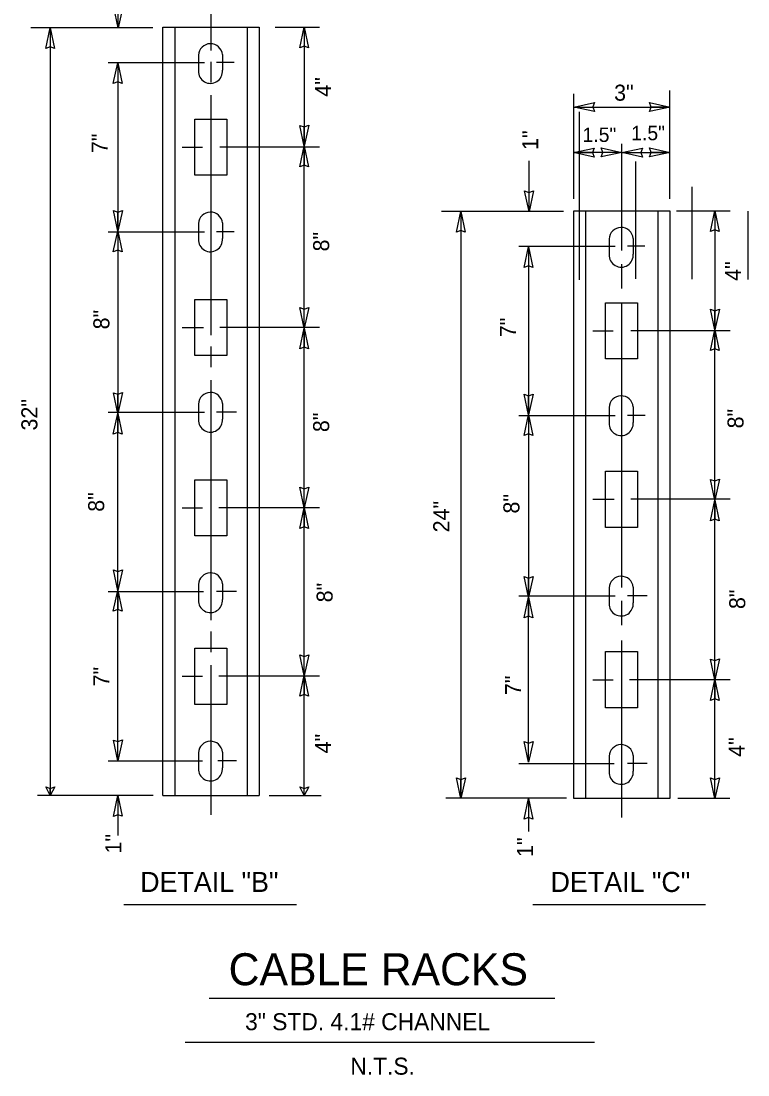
# Model space of a CAD drawing. Extents: x 19188 to 19495, y 20866 to 21061.
# Drawn here: x 19209.5 to 19245.3, y 20881.1 to 20932.9 of the extents above; entities that cross this region are included whole.
import ezdxf

# ---------------------------------------------------------------- set-up
doc = ezdxf.new("R2010")
doc.units = 0
doc.layers.add('G-ANNO-NOTE', color=7, linetype='Continuous')

msp = doc.modelspace()

# ---------------------------------------------------------------- linework, layer by layer
at = {"layer": 'G-ANNO-NOTE'}
for p, q in [((19214.31, 20932.566), (19214.31, 20935.058)), ((19214.31, 20932.566), (19214.31, 20933.502)), ((19216.005, 20932.566), (19210.015, 20932.566)), ((19210.966, 20932.566), (19210.966, 20894.812)), ((19210.966, 20932.566), (19210.966, 20931.63)), ((19216.507, 20932.592), (19221.237, 20932.592)), ((19216.507, 20894.812), (19216.507, 20932.592)), ((19217.098, 20894.812), (19217.098, 20932.592)), ((19220.645, 20932.592), (19220.645, 20894.812)), ((19221.237, 20932.592), (19221.237, 20894.812)), ((19222.022, 20932.598), (19224.196, 20932.598)), ((19223.449, 20932.598), (19223.449, 20926.749)), ((19223.449, 20932.598), (19223.449, 20931.662)), ((19218.247, 20931.206), (19218.247, 20930.417)), ((19219.429, 20931.242), (19219.429, 20930.473)), ((19213.809, 20930.857), (19218.55, 20930.857)), ((19214.289, 20930.832), (19214.29, 20922.564)), ((19214.289, 20930.832), (19214.289, 20929.896)), ((19220.011, 20930.857), (19219.145, 20930.857)), ((19236.689, 20924.149), (19236.689, 20929.309)), ((19241.419, 20924.149), (19241.419, 20929.486)), ((19236.689, 20928.666), (19241.437, 20928.666)), ((19236.689, 20928.666), (19237.625, 20928.666)), ((19241.437, 20928.666), (19240.5, 20928.666)), ((19218.069, 20928.073), (19219.646, 20928.073)), ((19218.069, 20925.314), (19218.069, 20928.073)), ((19219.646, 20928.073), (19219.646, 20925.314)), ((19236.964, 20928.421), (19236.964, 20920.177)), ((19236.964, 20928.421), (19236.964, 20920.177)), ((19223.449, 20926.749), (19223.449, 20927.685)), ((19217.454, 20926.694), (19218.441, 20926.694)), ((19224.196, 20926.694), (19219.308, 20926.694)), ((19223.449, 20917.789), (19223.449, 20926.749)), ((19223.449, 20926.749), (19223.449, 20925.812)), ((19234.493, 20923.531), (19234.493, 20926.023)), ((19239.054, 20926.432), (19236.683, 20926.432)), ((19236.683, 20926.432), (19237.619, 20926.432)), ((19239.054, 20926.432), (19238.118, 20926.432)), ((19239.054, 20926.432), (19241.437, 20926.432)), ((19239.054, 20926.432), (19239.991, 20926.432)), ((19239.73, 20925.981), (19239.73, 20920.224)), ((19239.73, 20925.981), (19239.73, 20920.224)), ((19241.437, 20926.432), (19240.5, 20926.432)), ((19219.646, 20925.314), (19218.069, 20925.314)), ((19234.493, 20923.531), (19234.493, 20924.467)), ((19242.495, 20924.743), (19242.495, 20920.206)), ((19242.495, 20924.743), (19242.495, 20920.206)), ((19214.29, 20922.564), (19214.29, 20923.501)), ((19236.187, 20923.531), (19230.198, 20923.531)), ((19231.149, 20923.531), (19231.149, 20894.67)), ((19231.149, 20923.531), (19231.149, 20922.595)), ((19236.689, 20923.558), (19241.419, 20923.558)), ((19236.689, 20894.67), (19236.689, 20923.558)), ((19237.28, 20894.67), (19237.28, 20923.558)), ((19240.828, 20923.558), (19240.828, 20894.67)), ((19241.419, 20923.558), (19241.419, 20894.67)), ((19241.746, 20923.564), (19244.378, 20923.564)), ((19243.631, 20923.564), (19243.631, 20917.714)), ((19243.631, 20923.564), (19243.631, 20922.627)), ((19245.25, 20923.548), (19245.25, 20920.191)), ((19245.25, 20923.548), (19245.25, 20920.191)), ((19218.247, 20922.928), (19218.247, 20922.14)), ((19219.429, 20922.964), (19219.429, 20922.195)), ((19213.81, 20922.533), (19218.55, 20922.534)), ((19214.29, 20922.564), (19214.291, 20913.605)), ((19214.29, 20922.564), (19214.29, 20921.628)), ((19220.011, 20922.534), (19219.145, 20922.534)), ((19233.992, 20921.822), (19238.732, 20921.822)), ((19238.429, 20922.171), (19238.429, 20921.382)), ((19240.193, 20921.822), (19239.328, 20921.822)), ((19239.612, 20922.207), (19239.612, 20921.438)), ((19234.471, 20921.798), (19234.472, 20913.53)), ((19234.471, 20921.798), (19234.471, 20920.862)), ((19218.069, 20919.205), (19219.646, 20919.205)), ((19218.069, 20916.445), (19218.069, 20919.205)), ((19219.646, 20919.205), (19219.646, 20916.445)), ((19223.449, 20917.789), (19223.449, 20918.725)), ((19238.251, 20919.039), (19239.828, 20919.039)), ((19238.251, 20916.28), (19238.251, 20919.039)), ((19239.828, 20919.039), (19239.828, 20916.28)), ((19243.631, 20917.714), (19243.631, 20918.65)), ((19217.455, 20917.825), (19218.495, 20917.825)), ((19224.196, 20917.825), (19219.308, 20917.825)), ((19223.449, 20908.956), (19223.449, 20917.789)), ((19223.449, 20917.789), (19223.449, 20916.853)), ((19243.631, 20909.346), (19243.631, 20917.714)), ((19243.631, 20917.714), (19243.631, 20916.778)), ((19237.637, 20917.659), (19238.624, 20917.659)), ((19244.378, 20917.659), (19239.49, 20917.659)), ((19219.646, 20916.445), (19218.069, 20916.445)), ((19239.828, 20916.28), (19238.251, 20916.28)), ((19214.291, 20913.605), (19214.29, 20914.541)), ((19218.247, 20914.059), (19218.247, 20913.271)), ((19219.429, 20914.095), (19219.429, 20913.326)), ((19234.472, 20913.53), (19234.472, 20914.466)), ((19213.81, 20913.665), (19218.55, 20913.665)), ((19214.291, 20904.899), (19214.291, 20913.605)), ((19214.291, 20913.605), (19214.291, 20912.668)), ((19220.118, 20913.665), (19219.145, 20913.665)), ((19234.472, 20913.53), (19234.473, 20904.57)), ((19234.472, 20913.53), (19234.472, 20912.594)), ((19238.429, 20913.893), (19238.429, 20913.105)), ((19239.612, 20913.929), (19239.612, 20913.16)), ((19233.992, 20913.499), (19238.732, 20913.499)), ((19240.194, 20913.499), (19239.328, 20913.499)), ((19238.251, 20910.761), (19239.828, 20910.761)), ((19238.251, 20908.002), (19238.251, 20910.761)), ((19239.828, 20910.761), (19239.828, 20908.002)), ((19218.069, 20910.336), (19219.646, 20910.336)), ((19218.069, 20907.577), (19218.069, 20910.336)), ((19219.646, 20910.336), (19219.646, 20907.577)), ((19243.631, 20909.346), (19243.631, 20910.282)), ((19223.449, 20908.956), (19223.449, 20909.892)), ((19237.637, 20909.381), (19238.678, 20909.381)), ((19244.378, 20909.382), (19239.49, 20909.381)), ((19217.455, 20908.956), (19218.441, 20908.956)), ((19224.196, 20908.956), (19219.254, 20908.956)), ((19223.449, 20900.715), (19223.449, 20908.956)), ((19223.449, 20908.956), (19223.449, 20908.02)), ((19243.631, 20900.513), (19243.631, 20909.346)), ((19243.631, 20909.346), (19243.631, 20908.409)), ((19239.828, 20908.002), (19238.251, 20908.002)), ((19219.646, 20907.577), (19218.069, 20907.577)), ((19214.291, 20904.899), (19214.291, 20905.835)), ((19234.473, 20904.57), (19234.472, 20905.506)), ((19213.811, 20904.842), (19218.495, 20904.842)), ((19214.291, 20896.53), (19214.291, 20904.899)), ((19214.291, 20904.899), (19214.291, 20903.962)), ((19218.247, 20905.19), (19218.247, 20904.402)), ((19220.118, 20904.842), (19219.145, 20904.842)), ((19219.429, 20905.226), (19219.429, 20904.458)), ((19238.429, 20905.025), (19238.429, 20904.236)), ((19239.612, 20905.061), (19239.612, 20904.292)), ((19233.992, 20904.63), (19238.732, 20904.631)), ((19234.473, 20896.455), (19234.473, 20904.57)), ((19234.473, 20904.57), (19234.473, 20903.634)), ((19240.3, 20904.631), (19239.328, 20904.631)), ((19218.069, 20902.058), (19219.646, 20902.058)), ((19218.069, 20899.299), (19218.069, 20902.058)), ((19219.646, 20902.058), (19219.646, 20899.299)), ((19223.449, 20900.715), (19223.449, 20901.651)), ((19238.251, 20901.892), (19239.828, 20901.892)), ((19238.251, 20899.133), (19238.251, 20901.892)), ((19239.828, 20901.892), (19239.828, 20899.133)), ((19243.631, 20900.513), (19243.631, 20901.449)), ((19217.455, 20900.679), (19218.441, 20900.679)), ((19224.196, 20900.679), (19219.254, 20900.679)), ((19223.449, 20900.715), (19223.449, 20899.778)), ((19223.449, 20894.812), (19223.449, 20900.715)), ((19237.637, 20900.513), (19238.624, 20900.513)), ((19244.378, 20900.513), (19239.436, 20900.513)), ((19243.631, 20900.513), (19243.631, 20899.577)), ((19243.631, 20894.67), (19243.631, 20900.513)), ((19219.646, 20899.299), (19218.069, 20899.299)), ((19239.828, 20899.133), (19238.251, 20899.133)), ((19214.291, 20896.53), (19214.291, 20897.467)), ((19219.429, 20896.949), (19219.429, 20896.18)), ((19234.473, 20896.455), (19234.473, 20897.391)), ((19213.812, 20896.518), (19218.441, 20896.519)), ((19218.247, 20896.913), (19218.247, 20896.125)), ((19220.119, 20896.519), (19219.2, 20896.519)), ((19238.429, 20896.747), (19238.429, 20895.959)), ((19239.612, 20896.783), (19239.612, 20896.014)), ((19233.993, 20896.398), (19238.678, 20896.398)), ((19240.301, 20896.399), (19239.328, 20896.398)), ((19231.149, 20894.67), (19231.149, 20895.606)), ((19243.631, 20894.67), (19243.631, 20895.606)), ((19210.966, 20894.812), (19210.966, 20895.158)), ((19223.449, 20894.812), (19223.449, 20895.158)), ((19216.032, 20894.812), (19210.335, 20894.812)), ((19214.292, 20894.812), (19214.292, 20892.854)), ((19214.292, 20894.812), (19214.292, 20893.876)), ((19216.507, 20894.812), (19221.237, 20894.812)), ((19221.728, 20894.812), (19224.286, 20894.812)), ((19236.334, 20894.687), (19230.41, 20894.687)), ((19234.473, 20894.67), (19234.474, 20893.048)), ((19234.473, 20894.67), (19234.474, 20893.734)), ((19241.419, 20894.67), (19236.689, 20894.67)), ((19241.803, 20894.687), (19244.367, 20894.687)), ((19214.581, 20889.468), (19223.071, 20889.468)), ((19234.684, 20889.468), (19243.174, 20889.468)), ((19218.77, 20884.853), (19235.767, 20884.853)), ((19217.592, 20882.698), (19237.705, 20882.698))]:
    msp.add_line(p, q, dxfattribs=at)
for points in [[(19218.872, 20931.451), (19218.872, 20935.886)], [(19214.31, 20933.503), (19214.534, 20933.584), (19214.31, 20932.566), (19214.097, 20933.582), (19214.31, 20933.503)], [(19210.966, 20931.63), (19210.743, 20931.548), (19210.966, 20932.566), (19211.18, 20931.55), (19210.966, 20931.63)], [(19223.449, 20931.662), (19223.224, 20931.58), (19223.449, 20932.598), (19223.662, 20931.582), (19223.449, 20931.662)], [(19214.289, 20929.896), (19214.066, 20929.814), (19214.289, 20930.832), (19214.503, 20929.816), (19214.289, 20929.896)], [(19218.872, 20929.876), (19218.872, 20930.893)], [(19218.872, 20921.879), (19218.872, 20929.241)], [(19237.626, 20928.667), (19237.708, 20928.443), (19236.689, 20928.666), (19237.705, 20928.88), (19237.626, 20928.667)], [(19240.5, 20928.666), (19240.418, 20928.89), (19241.437, 20928.666), (19240.421, 20928.453), (19240.5, 20928.666)], [(19223.449, 20927.685), (19223.672, 20927.767), (19223.449, 20926.749), (19223.235, 20927.765), (19223.449, 20927.685)], [(19223.449, 20925.812), (19223.224, 20925.73), (19223.449, 20926.749), (19223.662, 20925.733), (19223.449, 20925.812)], [(19237.619, 20926.433), (19237.701, 20926.208), (19236.683, 20926.432), (19237.7, 20926.646), (19237.619, 20926.433)], [(19238.118, 20926.432), (19238.036, 20926.656), (19239.054, 20926.432), (19238.038, 20926.219), (19238.118, 20926.432)], [(19239.054, 20921.609), (19239.054, 20926.851)], [(19239.991, 20926.433), (19240.072, 20926.208), (19239.054, 20926.432), (19240.07, 20926.646), (19239.991, 20926.433)], [(19240.5, 20926.432), (19240.418, 20926.656), (19241.437, 20926.432), (19240.421, 20926.219), (19240.5, 20926.432)], [(19234.492, 20924.467), (19234.717, 20924.549), (19234.493, 20923.531), (19234.279, 20924.548), (19234.492, 20924.467)], [(19214.29, 20923.501), (19214.513, 20923.583), (19214.29, 20922.564), (19214.076, 20923.58), (19214.29, 20923.501)], [(19231.149, 20922.595), (19230.925, 20922.513), (19231.149, 20923.531), (19231.362, 20922.515), (19231.149, 20922.595)], [(19243.631, 20922.627), (19243.407, 20922.545), (19243.631, 20923.564), (19243.844, 20922.548), (19243.631, 20922.627)], [(19214.29, 20921.628), (19214.066, 20921.546), (19214.29, 20922.564), (19214.503, 20921.548), (19214.29, 20921.628)], [(19218.872, 20917.445), (19218.872, 20921.879)], [(19234.471, 20920.862), (19234.248, 20920.78), (19234.471, 20921.798), (19234.685, 20920.781), (19234.471, 20920.862)], [(19239.054, 20919.747), (19239.054, 20920.948)], [(19223.449, 20918.725), (19223.672, 20918.807), (19223.449, 20917.789), (19223.235, 20918.805), (19223.449, 20918.725)], [(19239.054, 20910.293), (19239.054, 20918.996)], [(19243.631, 20918.651), (19243.855, 20918.733), (19243.631, 20917.714), (19243.417, 20918.73), (19243.631, 20918.651)], [(19223.449, 20916.853), (19223.224, 20916.771), (19223.449, 20917.789), (19223.662, 20916.773), (19223.449, 20916.853)], [(19243.631, 20916.778), (19243.407, 20916.696), (19243.631, 20917.714), (19243.844, 20916.698), (19243.631, 20916.778)], [(19218.872, 20915.869), (19218.872, 20916.885)], [(19218.872, 20907.872), (19218.872, 20915.234)], [(19214.29, 20914.541), (19214.514, 20914.623), (19214.291, 20913.605), (19214.076, 20914.621), (19214.29, 20914.541)], [(19234.472, 20914.466), (19234.695, 20914.548), (19234.472, 20913.53), (19234.258, 20914.546), (19234.472, 20914.466)], [(19214.291, 20912.668), (19214.066, 20912.586), (19214.291, 20913.605), (19214.504, 20912.589), (19214.291, 20912.668)], [(19234.472, 20912.593), (19234.248, 20912.511), (19234.472, 20913.53), (19234.685, 20912.514), (19234.472, 20912.593)], [(19223.449, 20909.892), (19223.672, 20909.974), (19223.449, 20908.956), (19223.235, 20909.972), (19223.449, 20909.892)], [(19239.054, 20905.051), (19239.054, 20910.293)], [(19243.631, 20910.282), (19243.855, 20910.364), (19243.631, 20909.346), (19243.417, 20910.362), (19243.631, 20910.282)], [(19223.449, 20908.019), (19223.224, 20907.938), (19223.449, 20908.956), (19223.662, 20907.94), (19223.449, 20908.019)], [(19243.631, 20908.409), (19243.407, 20908.327), (19243.631, 20909.346), (19243.844, 20908.33), (19243.631, 20908.409)], [(19218.872, 20903.438), (19218.872, 20907.872)], [(19214.291, 20905.835), (19214.515, 20905.917), (19214.291, 20904.899), (19214.077, 20905.915), (19214.291, 20905.835)], [(19234.472, 20905.507), (19234.696, 20905.589), (19234.473, 20904.57), (19234.259, 20905.586), (19234.472, 20905.507)], [(19214.291, 20903.962), (19214.067, 20903.88), (19214.291, 20904.899), (19214.505, 20903.883), (19214.291, 20903.962)], [(19234.473, 20903.634), (19234.249, 20903.552), (19234.473, 20904.57), (19234.686, 20903.554), (19234.473, 20903.634)], [(19239.054, 20903.189), (19239.054, 20904.39)], [(19218.872, 20901.863), (19218.872, 20902.879)], [(19239.054, 20893.735), (19239.054, 20902.438)], [(19223.449, 20901.651), (19223.672, 20901.733), (19223.449, 20900.715), (19223.235, 20901.731), (19223.449, 20901.651)], [(19218.872, 20893.866), (19218.872, 20901.228)], [(19243.631, 20901.449), (19243.855, 20901.531), (19243.631, 20900.513), (19243.417, 20901.529), (19243.631, 20901.449)], [(19223.449, 20899.778), (19223.224, 20899.696), (19223.449, 20900.715), (19223.662, 20899.698), (19223.449, 20899.778)], [(19243.631, 20899.576), (19243.407, 20899.494), (19243.631, 20900.513), (19243.844, 20899.497), (19243.631, 20899.576)], [(19214.291, 20897.467), (19214.516, 20897.548), (19214.291, 20896.53), (19214.078, 20897.546), (19214.291, 20897.467)], [(19234.473, 20897.392), (19234.697, 20897.474), (19234.473, 20896.455), (19234.259, 20897.471), (19234.473, 20897.392)], [(19231.148, 20895.607), (19231.372, 20895.689), (19231.149, 20894.67), (19230.935, 20895.686), (19231.148, 20895.607)], [(19243.631, 20895.607), (19243.855, 20895.689), (19243.631, 20894.67), (19243.417, 20895.686), (19243.631, 20895.607)], [(19210.966, 20895.158), (19211.19, 20895.239), (19210.966, 20894.812), (19210.753, 20895.237), (19210.966, 20895.158)], [(19223.449, 20895.158), (19223.672, 20895.239), (19223.449, 20894.812), (19223.235, 20895.237), (19223.449, 20895.158)], [(19214.292, 20893.876), (19214.068, 20893.794), (19214.292, 20894.812), (19214.506, 20893.796), (19214.292, 20893.876)], [(19234.474, 20893.734), (19234.25, 20893.652), (19234.473, 20894.67), (19234.687, 20893.654), (19234.474, 20893.734)]]:
    msp.add_lwpolyline(points, dxfattribs=at)
for centre, start, end in [((19218.841, 20931.187), 5.267, 177.6123), ((19218.841, 20930.418), 177.6721, 5.267), ((19218.841, 20922.91), 5.267, 177.6123), ((19239.023, 20922.153), 5.267, 177.6123), ((19218.841, 20922.141), 177.6721, 5.267), ((19239.023, 20921.384), 177.6721, 5.267), ((19218.841, 20914.041), 5.267, 177.6123), ((19239.023, 20913.875), 5.267, 177.6123), ((19218.841, 20913.272), 177.6721, 5.267), ((19239.023, 20913.106), 177.6721, 5.267), ((19218.841, 20905.172), 5.267, 177.6123), ((19239.023, 20905.006), 5.267, 177.6123), ((19218.841, 20904.403), 177.6721, 5.267), ((19239.023, 20904.237), 177.6721, 5.267), ((19218.841, 20896.895), 5.267, 177.6123), ((19239.023, 20896.729), 5.267, 177.6123), ((19218.841, 20896.126), 177.6721, 5.267), ((19239.023, 20895.96), 177.6721, 5.267)]:
    msp.add_arc(centre, 0.591, start, end, dxfattribs=at)

# ---------------------------------------------------------------- texts
for s, p in [('4"', (19224.77, 20929.173)), ('7"', (19213.789, 20926.401)), ('1"', (19234.946, 20926.555)), ('8"', (19224.673, 20921.566)), ('4"', (19244.918, 20920.12)), ('8"', (19213.874, 20917.734)), ('7"', (19233.851, 20917.348)), ('32"', (19210.335, 20912.762)), ('8"', (19224.673, 20912.684)), ('8"', (19245.035, 20912.866)), ('8"', (19213.618, 20908.767)), ('8"', (19234.022, 20908.681)), ('24"', (19230.574, 20907.756)), ('8"', (19224.843, 20904.315)), ('8"', (19245.12, 20903.984)), ('7"', (19213.874, 20900.183)), ('7"', (19234.107, 20899.756)), ('4"', (19224.77, 20896.891)), ('4"', (19245.089, 20896.72)), ('1"', (19214.458, 20891.968)), ('1"', (19234.69, 20891.797))]:
    msp.add_text(s, height=0.7883, rotation=90, dxfattribs=at).set_placement(p)
for s, height, p in [('3"', 0.7883, (19238.675, 20928.976)), ('1.5"', 0.7095, (19237.127, 20926.948)), ('1.5"', 0.7095, (19239.518, 20927.034)), ('DETAIL "B"', 0.9854, (19215.388, 20890.077)), ('DETAIL "C"', 0.9854, (19235.553, 20890.077)), ('CABLE RACKS', 1.57098, (19219.732, 20885.492)), ('3" STD. 4.1# CHANNEL', 0.83785, (19220.542, 20883.281)), ('N.T.S.', 0.8379, (19225.712, 20881.094))]:
    msp.add_text(s, height=height, dxfattribs=at).set_placement(p)

doc.saveas('drawing.dxf')
